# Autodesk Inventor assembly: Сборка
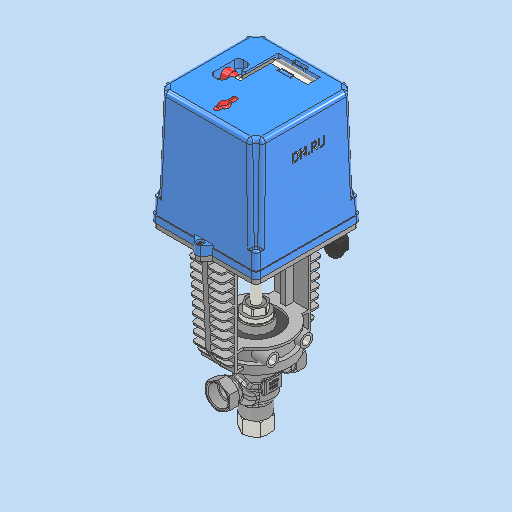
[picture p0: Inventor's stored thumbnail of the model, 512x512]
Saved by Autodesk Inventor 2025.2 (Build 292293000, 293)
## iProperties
Created: 2026-04
Part Number: Сборка
Document SubType Name: Assembly
Designer: igorr
Author: igorr
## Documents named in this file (7)
- D:\PROJECT CAD\DN.RU\...197(ACTUALE). VRg3M-S-31M-PED-T Клапан регулирующий трехходовой DN.ru\Исходники\DN20\Сборка.iam
- D:\PROJECT CAD\DN.RU\...197(ACTUALE). VRg3M-S-31M-PED-T Клапан регулирующий трехходовой DN.ru\Исходники\DN20\Деталь 1.ipt
- D:\PROJECT CAD\DN.RU\...197(ACTUALE). VRg3M-S-31M-PED-T Клапан регулирующий трехходовой DN.ru\Исходники\DN20\Деталь 2.ipt
- D:\PROJECT CAD\DN.RU\...197(ACTUALE). VRg3M-S-31M-PED-T Клапан регулирующий трехходовой DN.ru\Исходники\DN20\Деталь 3.ipt
- C:\Users\igorr\OneDrive\Документы\Inventor\Content Center Files\R2025\ru-RU\AS 1421(2)\AS 1421 - M10 x 12 засверленный конец.ipt
- C:\Users\igorr\OneDrive\Документы\Inventor\Content Center Files\R2025\ru-RU\AS 1420\AS 1420 - 1973 - M5 x 10.ipt
- C:\Users\igorr\OneDrive\Документы\Inventor\Content Center Files\R2025\ru-RU\AS 1427(05)\AS 1427 - M3 x 8(5) II.ipt
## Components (8 placed, 6 different names)
1. Деталь 1:1 — Касательность:1, Касательность:2, Угол:1, Совмещение:1, Совмещение:5, Угол:3, Заподлицо:1, Совмещение:8, Совмещение:10, Совмещение:11
2. Деталь 2:1 — Касательность:1, Касательность:2, Угол:1, Совмещение:1
3. Деталь 3:1 — Совмещение:2, Совмещение:3, Угол:2, Совмещение:5, Угол:3, Совмещение:11
4. AS 1421 засверленный конец - метрическая M10 x 12 засверленный конец:1 — Заподлицо:1
5. AS 1420 - метрическая M5 x 10:1 — Совмещение:8
6. AS 1420 - метрическая M5 x 10:2 — Совмещение:10
7. AS 1427 H - метрическая M3 x 8:1
8. AS 1427 H - метрическая M3 x 8:2
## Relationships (13: Mate 7, Angle 3, Tangent 2, Flush 1)
- Касательность:1 [Tangent]: Деталь 1:1 ↔ Деталь 2:1
- Касательность:2 [Tangent]: Деталь 1:1 ↔ Деталь 2:1
- Угол:1 [Angle]: Деталь 1:1 ↔ Деталь 2:1
- Совмещение:1 [Mate]: Деталь 1:1 ↔ Деталь 2:1
- Совмещение:2 [Mate]: Деталь 3:1
- Совмещение:3 [Mate]: Деталь 3:1
- Угол:2 [Angle]: Деталь 3:1
- Совмещение:5 [Mate]: Деталь 1:1 ↔ Деталь 3:1
- Угол:3 [Angle]: Деталь 1:1 ↔ Деталь 3:1
- Заподлицо:1 [Flush]: Деталь 1:1 ↔ AS 1421 засверленный конец - метрическая M10 x 12 засверленный конец:1
- Совмещение:8 [Mate]: Деталь 1:1 ↔ AS 1420 - метрическая M5 x 10:1
- Совмещение:10 [Mate]: Деталь 1:1 ↔ AS 1420 - метрическая M5 x 10:2
- Совмещение:11 [Mate]: Деталь 1:1 ↔ Деталь 3:1
